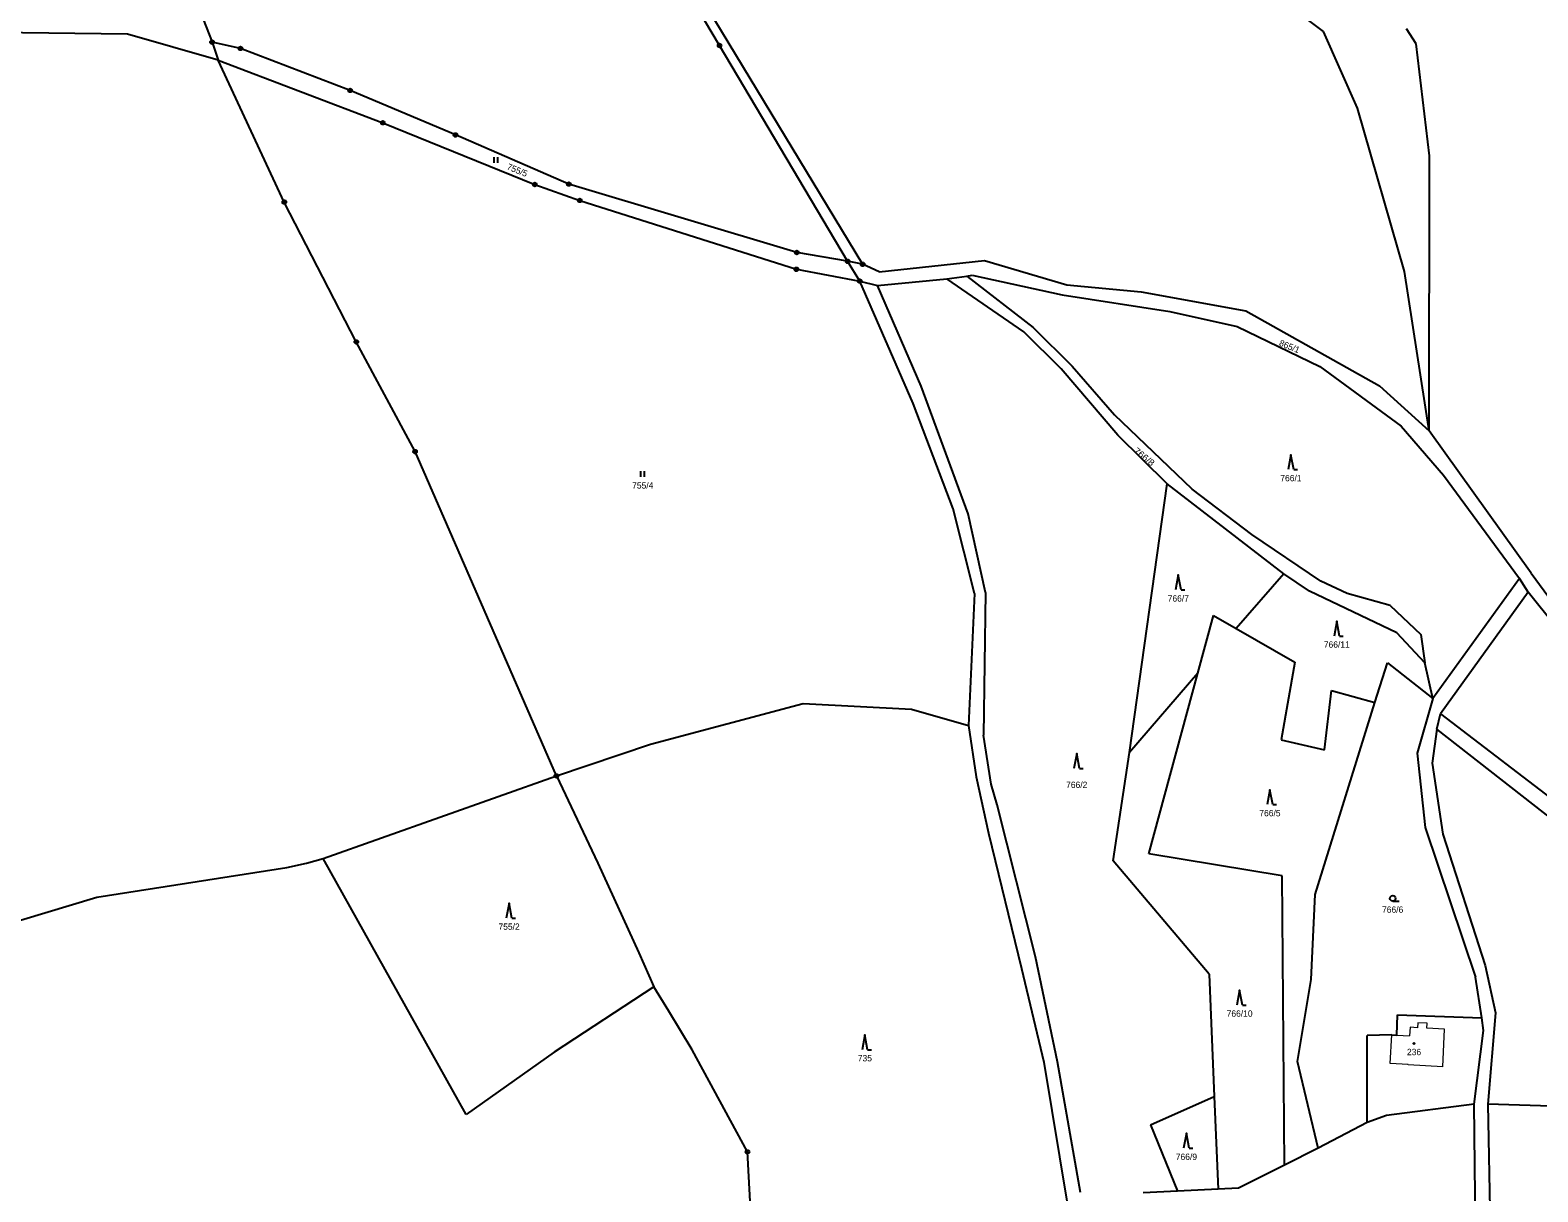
# Model space of a CAD drawing. Extents: x -739410 to -735662, y -942282 to -940043.
# Drawn here: x -738202.6 to -737798.5, y -940620.7 to -940309.4 of the extents above; entities that cross this region are included whole.
import ezdxf
from ezdxf.enums import TextEntityAlignment as Align

# ---------------------------------------------------------------- set-up
doc = ezdxf.new("R2010")
doc.units = 0
doc.header["$LTSCALE"] = 0.68
for name, color, linetype, lineweight in [('1', 7, 'Continuous', 25), ('3', 7, 'Continuous', 25), ('4', 7, 'Continuous', 13), ('5', 7, 'Continuous', 25), ('8', 7, 'Continuous', 25)]:
    doc.layers.add(name, color=color, linetype=linetype, lineweight=lineweight)
doc.layers.add('2', color=7, linetype='Continuous')

msp = doc.modelspace()

# ---------------------------------------------------------------- linework, layer by layer
at = {"layer": '1'}
for p, q in [((-738167.55, -940277.41), (-738153.83, -940312.62)), ((-738017.82, -940313.52), (-738033.46, -940287.31)), ((-737855.98, -940309.76), (-737885.6, -940287.33)), ((-738024.17, -940298.37), (-737979.47, -940372.15)), ((-738176.45, -940310.44), (-738234.66, -940309.72)), ((-738152.14, -940317.46), (-738176.45, -940310.44)), ((-738153.83, -940312.62), (-738152.14, -940317.46)), ((-738146.18, -940314.31), (-738153.83, -940312.62)), ((-737846.9, -940330.27), (-737855.98, -940309.76)), ((-737831.14, -940313.08), (-737833.72, -940309.09)), ((-738116.82, -940325.56), (-738146.18, -940314.31)), ((-737983.51, -940371.35), (-738017.82, -940313.52)), ((-737827.53, -940343.05), (-737831.14, -940313.08)), ((-738134.46, -940355.46), (-738152.14, -940317.46)), ((-738152.14, -940317.46), (-738108.04, -940334.22)), ((-738088.58, -940337.49), (-738116.82, -940325.56)), ((-737834.26, -940374.11), (-737846.9, -940330.27)), ((-738108.04, -940334.22), (-738067.32, -940350.76)), ((-738058.21, -940350.65), (-738088.58, -940337.49)), ((-737827.62, -940416.82), (-737827.53, -940343.05)), ((-738067.32, -940350.76), (-738055.28, -940355.04)), ((-737997.12, -940368.99), (-738058.21, -940350.65)), ((-738115.16, -940392.95), (-738134.46, -940355.46)), ((-738055.28, -940355.04), (-737997.23, -940373.49)), ((-737983.51, -940371.35), (-737997.12, -940368.99)), ((-737997.23, -940373.49), (-737980.24, -940376.64)), ((-737979.47, -940372.15), (-737983.51, -940371.35)), ((-737980.24, -940376.64), (-737983.51, -940371.35)), ((-737975.07, -940374.18), (-737979.47, -940372.15)), ((-737975.07, -940374.18), (-737946.82, -940371.1)), ((-737946.82, -940371.1), (-737924.73, -940377.68)), ((-737980.24, -940376.64), (-737975.53, -940377.86)), ((-737965.94, -940409.44), (-737980.24, -940376.64)), ((-737975.53, -940377.86), (-737956.95, -940376.02)), ((-737956.95, -940376.02), (-737951.56, -940375.3)), ((-737936.25, -940390.28), (-737956.95, -940376.02)), ((-737951.56, -940375.3), (-737950.1, -940375.1)), ((-737951.56, -940375.3), (-737933.75, -940389.11)), ((-737950.1, -940375.1), (-737926.02, -940380.32)), ((-737924.73, -940377.68), (-737904.82, -940379.55)), ((-737827.62, -940416.82), (-737834.26, -940374.11)), ((-737963.81, -940404.81), (-737975.53, -940377.86)), ((-737926.02, -940380.32), (-737897.15, -940384.84)), ((-737904.82, -940379.55), (-737876.82, -940384.64)), ((-737897.15, -940384.84), (-737879.07, -940388.83)), ((-737876.82, -940384.64), (-737841, -940404.68)), ((-737933.75, -940389.11), (-737923.37, -940399.47)), ((-737879.07, -940388.83), (-737856.92, -940399.52)), ((-738099.4, -940422.35), (-738115.16, -940392.95)), ((-737926.26, -940400.2), (-737936.25, -940390.28)), ((-737911.05, -940417.96), (-737926.26, -940400.2)), ((-737923.37, -940399.47), (-737912.02, -940412.5)), ((-737856.92, -940399.52), (-737835.2, -940415.5)), ((-737951.18, -940438.98), (-737963.81, -940404.81)), ((-737841, -940404.68), (-737827.62, -940416.82)), ((-737955.2, -940437.69), (-737965.94, -940409.44)), ((-737891.19, -940432.42), (-737912.02, -940412.5)), ((-737897.89, -940430.96), (-737911.05, -940417.96)), ((-737835.2, -940415.5), (-737823.86, -940428.62)), ((-737800.34, -940454.93), (-737827.62, -940416.82)), ((-738061.55, -940509.25), (-738099.4, -940422.35)), ((-737823.86, -940428.62), (-737803.49, -940456.36)), ((-737907.95, -940502.96), (-737897.89, -940430.96)), ((-737866.64, -940455.1), (-737897.89, -940430.96)), ((-737875.22, -940444.53), (-737891.19, -940432.42)), ((-737949.5, -940460.39), (-737955.2, -940437.69)), ((-737946.58, -940460.07), (-737951.18, -940438.98)), ((-737856.68, -940457.04), (-737875.22, -940444.53)), ((-737866.64, -940455.1), (-737879.37, -940469.79)), ((-737859.7, -940459.76), (-737866.64, -940455.1)), ((-737849.65, -940460.41), (-737856.68, -940457.04)), ((-737803.49, -940456.36), (-737826.72, -940488.5)), ((-737801.11, -940460.02), (-737803.49, -940456.36)), ((-737800.34, -940454.93), (-737792.34, -940465.71)), ((-737949.5, -940460.39), (-737951.07, -940495.71)), ((-737946.58, -940460.07), (-737947.05, -940498.31)), ((-737836.31, -940470.92), (-737859.7, -940459.76)), ((-737838.13, -940463.61), (-737849.65, -940460.41)), ((-737801.11, -940460.02), (-737824.58, -940492.63)), ((-737793.91, -940469.06), (-737801.11, -940460.02)), ((-737889.66, -940481.76), (-737885.47, -940466.28)), ((-737885.47, -940466.28), (-737879.37, -940469.79)), ((-737838.13, -940463.61), (-737829.85, -940471.34)), ((-737879.37, -940469.79), (-737863.7, -940478.79)), ((-737828.86, -940478.93), (-737836.31, -940470.92)), ((-737829.85, -940471.34), (-737828.86, -940478.93)), ((-737889.66, -940481.76), (-737907.95, -940502.96)), ((-737902.75, -940530.11), (-737889.66, -940481.76)), ((-737863.7, -940478.79), (-737867.35, -940499.59)), ((-737842.18, -940489.54), (-737838.82, -940478.92)), ((-737838.82, -940478.92), (-737826.72, -940488.5)), ((-737826.72, -940488.5), (-737828.86, -940478.93)), ((-737855.69, -940502.26), (-737853.87, -940486.38)), ((-737853.87, -940486.38), (-737842.18, -940489.54)), ((-738036.32, -940500.73), (-737995.43, -940489.82)), ((-737995.43, -940489.82), (-737966.38, -940491.38)), ((-737858.17, -940541.06), (-737842.18, -940489.54)), ((-737826.72, -940488.5), (-737830.85, -940503.12)), ((-737966.38, -940491.38), (-737951.07, -940495.71)), ((-737951.07, -940495.71), (-737949.03, -940509.48)), ((-737944.99, -940511.46), (-737947.05, -940498.31)), ((-737825.64, -940496.73), (-737826.83, -940505.82)), ((-737794.14, -940521.27), (-737825.64, -940496.73)), ((-738061.55, -940509.25), (-738036.32, -940500.73)), ((-737912.34, -940532.04), (-737907.95, -940502.96)), ((-737867.35, -940499.59), (-737855.69, -940502.26)), ((-737830.85, -940503.12), (-737828.75, -940523.05)), ((-737826.83, -940505.82), (-737824.01, -940524.88)), ((-738124.02, -940531.36), (-738061.55, -940509.25)), ((-738061.55, -940509.25), (-738050.45, -940532.67)), ((-737949.03, -940509.48), (-737945.76, -940524.63)), ((-737943.44, -940517.01), (-737944.99, -940511.46)), ((-737933.19, -940557.77), (-737943.44, -940517.01)), ((-737828.75, -940523.05), (-737815.22, -940563.15)), ((-737945.76, -940524.63), (-737936.87, -940560.87)), ((-737824.01, -940524.88), (-737812.62, -940560.02)), ((-737867.07, -940536.01), (-737902.75, -940530.11)), ((-738184.7, -940541.74), (-738133.78, -940533.77)), ((-738133.78, -940533.77), (-738128.52, -940532.6)), ((-738128.52, -940532.6), (-738124.02, -940531.36)), ((-738085.73, -940599.96), (-738124.02, -940531.36)), ((-738050.45, -940532.67), (-738039.49, -940556.63)), ((-737886.64, -940562.42), (-737912.34, -940532.04)), ((-737866.39, -940613.54), (-737867.07, -940536.01)), ((-738214.49, -940550.75), (-738184.7, -940541.74)), ((-737859.25, -940563.79), (-737858.17, -940541.06)), ((-738039.49, -940556.63), (-738035.46, -940565.81)), ((-737927.26, -940585.88), (-737933.19, -940557.77)), ((-737936.87, -940560.87), (-737930.94, -940585.95)), ((-737886.64, -940562.42), (-737885.25, -940595.15)), ((-737813.58, -940574.1), (-737815.22, -940563.15)), ((-737812.62, -940560.02), (-737809.92, -940572.76)), ((-738035.46, -940565.81), (-738062.13, -940583.32)), ((-738031.44, -940572.25), (-738035.46, -940565.81)), ((-737862.97, -940585.78), (-737859.25, -940563.79)), ((-738025.18, -940582.64), (-738031.44, -940572.25)), ((-737836.31, -940578.7), (-737836.15, -940573.29)), ((-737836.15, -940573.29), (-737813.58, -940574.1)), ((-737813.08, -940577.47), (-737813.58, -940574.1)), ((-737809.92, -940572.76), (-737811.98, -940597.17)), ((-737837.7, -940578.62), (-737844.3, -940578.8)), ((-737844.3, -940602.14), (-737844.3, -940578.8)), ((-737837.7, -940578.62), (-737836.31, -940578.7)), ((-737815.58, -940597.21), (-737813.08, -940577.47)), ((-738062.13, -940583.32), (-738085.73, -940599.96)), ((-738010.34, -940610), (-738025.18, -940582.64)), ((-737930.94, -940585.95), (-737924.62, -940624.25)), ((-737921.07, -940620.9), (-737927.26, -940585.88)), ((-737857.39, -940609.02), (-737862.97, -940585.78)), ((-737902.33, -940602.76), (-737885.25, -940595.15)), ((-737885.25, -940595.15), (-737884.2, -940619.99)), ((-737815.58, -940597.21), (-737839.12, -940600.22)), ((-737815.18, -940636.19), (-737815.58, -940597.21)), ((-737811.98, -940597.17), (-737811.05, -940642.82)), ((-737794.93, -940597.71), (-737811.98, -940597.17)), ((-737902.33, -940602.76), (-737895.09, -940620.52)), ((-737844.3, -940602.14), (-737857.39, -940609.02)), ((-737839.12, -940600.22), (-737844.3, -940602.14)), ((-738007.61, -940658.52), (-738010.34, -940610)), ((-737857.39, -940609.02), (-737866.39, -940613.54)), ((-737866.39, -940613.54), (-737878.75, -940619.73)), ((-737884.2, -940619.99), (-737895.09, -940620.52)), ((-737878.75, -940619.73), (-737884.2, -940619.99)), ((-737895.09, -940620.52), (-737904.34, -940620.97))]:
    msp.add_line(p, q, dxfattribs=at)
msp.add_lwpolyline([(-737825.64, -940496.73), (-737824.58, -940492.63), (-737790.75, -940518.52)], dxfattribs=at)
at = {"layer": '3'}
for p, q in [((-738078.261, -940344.95), (-738078.261, -940343.45)), ((-738077.26, -940344.95), (-738077.26, -940343.45)), ((-738038.911, -940429.12), (-738038.911, -940427.62)), ((-738037.91, -940429.12), (-738037.91, -940427.62)), ((-737863.96, -940427.18), (-737862.964, -940427.18)), ((-737894.13, -940459.41), (-737893.134, -940459.41)), ((-737851.66, -940471.77), (-737850.664, -940471.77)), ((-737921.35, -940507.27), (-737920.354, -940507.27)), ((-737869.58, -940516.95), (-737868.584, -940516.95)), ((-737837.433, -940542.81), (-737835.683, -940542.81)), ((-738073.47, -940547.37), (-738072.474, -940547.37)), ((-737877.7, -940570.66), (-737876.704, -940570.66)), ((-737978.13, -940582.62), (-737977.134, -940582.62)), ((-737891.96, -940609.03), (-737890.964, -940609.03))]:
    msp.add_line(p, q, dxfattribs=at)
for points in [[(-737863.96, -940427.18), (-737864.71, -940423.18), (-737865.46, -940427.18)], [(-737894.13, -940459.41), (-737894.88, -940455.41), (-737895.63, -940459.41)], [(-737851.66, -940471.77), (-737852.41, -940467.77), (-737853.16, -940471.77)], [(-737921.35, -940507.27), (-737922.1, -940503.27), (-737922.85, -940507.27)], [(-737869.58, -940516.95), (-737870.33, -940512.95), (-737871.08, -940516.95)], [(-738073.47, -940547.37), (-738074.22, -940543.37), (-738074.97, -940547.37)], [(-737877.7, -940570.66), (-737878.45, -940566.66), (-737879.2, -940570.66)], [(-737978.13, -940582.62), (-737978.88, -940578.62), (-737979.63, -940582.62)], [(-737891.96, -940609.03), (-737892.71, -940605.03), (-737893.46, -940609.03)]]:
    msp.add_lwpolyline(points, dxfattribs=at)
msp.add_circle((-737837.4329, -940542.0598), 0.75, dxfattribs=at)
at = {"layer": '4'}
for p, q in [((-737830.71, -940575.39), (-737830.79, -940576.72)), ((-737828.18, -940575.53), (-737830.71, -940575.39)), ((-737828.25, -940576.84), (-737828.18, -940575.53)), ((-737838.12, -940586.3), (-737837.7, -940578.62)), ((-737836.31, -940578.7), (-737832.92, -940578.88)), ((-737832.78, -940576.61), (-737832.92, -940578.88)), ((-737830.79, -940576.72), (-737832.78, -940576.61)), ((-737823.54, -940577.11), (-737828.25, -940576.84)), ((-737824.03, -940587.19), (-737823.54, -940577.11)), ((-737833.31, -940586.56), (-737838.12, -940586.3)), ((-737833.3, -940586.65), (-737833.31, -940586.56)), ((-737824.03, -940587.19), (-737833.3, -940586.65))]:
    msp.add_line(p, q, dxfattribs=at)
at = {"layer": '5'}
msp.add_circle((-737831.7168, -940580.9592), 0.175, dxfattribs=at)
at = {"layer": '8'}
for centre, radius in [((-738153.83, -940312.6199), 0.5), ((-738153.83, -940312.6199), 0.0303), ((-738017.82, -940313.5199), 0.5), ((-738146.18, -940314.3099), 0.5), ((-738146.18, -940314.3099), 0.0303), ((-738017.82, -940313.5199), 0.0303), ((-738116.82, -940325.5599), 0.5), ((-738116.82, -940325.5599), 0.0303), ((-738108.04, -940334.2199), 0.5), ((-738108.04, -940334.2199), 0.0303), ((-738088.58, -940337.4899), 0.5), ((-738088.58, -940337.4899), 0.0303), ((-738067.32, -940350.7599), 0.5), ((-738067.32, -940350.7599), 0.0303), ((-738058.21, -940350.6499), 0.5), ((-738058.21, -940350.6499), 0.0303), ((-738134.46, -940355.4599), 0.5), ((-738134.46, -940355.4599), 0.0303), ((-738055.28, -940355.0399), 0.5), ((-738055.28, -940355.0399), 0.0303), ((-737997.12, -940368.9899), 0.5), ((-737997.12, -940368.9899), 0.0303), ((-737997.23, -940373.4899), 0.5), ((-737997.23, -940373.4899), 0.0303), ((-737983.51, -940371.3499), 0.5), ((-737983.51, -940371.3499), 0.0303), ((-737979.47, -940372.1499), 0.5), ((-737979.47, -940372.1499), 0.0303), ((-737980.24, -940376.6399), 0.5), ((-737980.24, -940376.6399), 0.0303), ((-738115.16, -940392.9499), 0.5), ((-738115.16, -940392.9499), 0.0303), ((-738099.4, -940422.3499), 0.5), ((-738099.4, -940422.3499), 0.0303), ((-738061.55, -940509.2499), 0.5), ((-738061.55, -940509.2499), 0.0303), ((-738010.34, -940609.9999), 0.5), ((-738010.34, -940609.9999), 0.0303)]:
    msp.add_circle(centre, radius, dxfattribs=at)

# ---------------------------------------------------------------- texts
at = {"layer": '2'}
for s, p in [('755/5', (-738072.3464, -940347.7089)), ('865/1', (-737865.3964, -940394.9489))]:
    msp.add_text(s, height=1.7, rotation=338, dxfattribs=at).set_placement(p, align=Align.CENTER)
at = {"layer": '2', "width": 1.1}
msp.add_text('766/8', height=1.7, rotation=321, dxfattribs=at).set_placement((-737904.5344, -940424.3805), align=Align.CENTER)
at = {"layer": '2'}
for s, p in [('766/1', (-737864.71, -940430.305)), ('755/4', (-738038.4, -940432.245)), ('766/7', (-737894.88, -940462.535)), ('766/11', (-737852.41, -940474.895)), ('766/2', (-737922.1, -940512.475)), ('766/5', (-737870.33, -940520.075)), ('766/6', (-737837.44, -940545.935)), ('755/2', (-738074.22, -940550.495)), ('766/10', (-737878.45, -940573.785)), ('236', (-737831.709, -940584.085)), ('735', (-737978.879, -940585.745)), ('766/9', (-737892.71, -940612.155))]:
    msp.add_text(s, height=1.7, dxfattribs=at).set_placement(p, align=Align.CENTER)

doc.saveas('drawing.dxf')
